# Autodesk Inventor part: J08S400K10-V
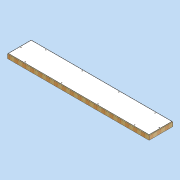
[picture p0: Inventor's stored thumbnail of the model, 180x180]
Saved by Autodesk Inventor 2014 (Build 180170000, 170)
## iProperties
Created: 2011-04
Part Number: J08S400K10-V
Document SubType Name: Modeling
Designer: david.appleford
Density: 1 g/cm^3
Description: Joist Spacer 2w x 400mm Locks 10
Mass: 75032.5 g
Surface Area: 23468.7 cm^2
Volume: 75032.5 cm^3
Cost Center: £95.00
Material: Generic
Appearance: Wood (Pine)
Justset: False
Title: Panel 0.5w x 1w Locks 3
Author: david.appleford
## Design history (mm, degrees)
sketch "Sketch1"
  geometry: L1 (0, 0)-(2440, 0); L2 (2440, 0)-(2440, 468); L3 (2440, 468)-(0, 468); L4 (0, 468)-(0, 0); L5 (34, 434)-(2406, 434); L6 (2406, 434)-(2406, 34); L7 (2406, 34)-(34, 34); L8 (34, 34)-(34, 434)
  constraints: 16 end point, 4 parallel, 2 perpendicular, 1 horizontal, 3 other
  dimensions: "d0" = 2440 distance between parallel lines of L2 L4; "d1" = 468 distance between parallel lines of L1 L3; "d2" = 34 distance between parallel lines of L5 L3 (= 0.5 x t); "d30" = 400 distance between parallel lines of L7 L5 (derived); "d31" = 2372 distance between parallel lines of L6 L8 (derived)
extrude "Extrusion1" new body sketch "Sketch1" distance "d3" = 68 (= t); taper "d4" = 0 deg
sketch "Sketch2"
  geometry: L1 (2406, 434)-(2406, 34) reference; L2 (34, 434)-(2406, 434) reference; L3 (34, 34)-(34, 434) reference; L4 (2406, 34)-(34, 34) reference; L5 (2396, 424)-(2396, 44); L6 (2396, 44)-(44, 44); L7 (44, 44)-(44, 424); L8 (44, 424)-(2396, 424); 1 further point
  constraints: 8 end point, 3 other
  dimensions: "d5" = 10 distance between parallel lines of L8 L2
extrude "Extrusion2" join sketch "Sketch2" distance "d6" = 6 (= sw); taper "d7" = 0 deg
sketch "Sketch3"
  geometry: L1 (-44, 424)-(-2396, 424) reference; L2 (-2396, 424)-(-2396, 44) reference; L3 (-44, 44)-(-44, 424) reference; L4 (-2396, 44)-(-44, 44) reference; 1 further point
extrude "Extrusion3" join sketch "Sketch3" distance "d8" = 6 (= sw); taper "d9" = 0 deg
sketch "Sketch4" dims "d39" = 10
  geometry: L1 (34, 434)-(2406, 434) reference; L2 (2406, 434)-(2406, 34) reference; L3 (2406, 34)-(34, 34) reference; L4 (34, 34)-(34, 434) reference; 11 further points
  constraints: 3 horizontal alignment, 2 vertical alignment, 1 horizontal, 4 other
  dimensions: "d10" = 28 distance from line of point (305, 406) L1 (= k); "d12" = 28 distance from line of L3 point (915, 62) (= k); "d13" = 28 distance from line of point (62, 234) L4 (= k); "d14" = 305 horizontal distance of point (305, 406) point (0, 0) (= 0.25 x w); "d15" = 610 horizontal distance of point (915, 62) point (305, 406) (= 0.5 x w); "d29" = 28 distance from line of L2 point (2378, 234) (= d13); "d32" = 400 distance between parallel lines of L3 L1 (derived); "d33" = 200 distance from line of L1 point (62, 234) (= 0.5 x d32); "d36" = 1220 distance of point (305, 406) point (1525, 406)
hole "Hole1" sketch "Sketch4" at (305, 406), (62, 234), (915, 62), (2378, 234), (915, 406), (305, 62), (1525, 406), (1525, 62), (2135, 406), (2135, 62) diameter "d22" = 12 (= hd); stored, may be unused: countersink angle "d26" = 90 deg, drill point angle "d28" = 118 deg; dims "d23" = 6, "d24" = 4, "d25" = 2, "d27" = 8
sketch "Sketch5"
  geometry: L1 (-2406, 34)-(-34, 34) reference; L2 (-34, 434)-(-2406, 434) reference; L3 (-1176, 34)-(-1264, 34); L4 (-1264, 34)-(-1264, 434); L5 (-1264, 434)-(-1176, 434); L6 (-1176, 434)-(-1176, 34); L7 (-1220, 34)-(-1220, 434); 1 further point
  constraints: 10 end point, 2 midpoint, 2 point on line
  dimensions: "d41" = 1220 distance from line of L7 point (0, 0); "d42" = 88 distance between parallel lines of L4 L6
extrude "Extrusion4" cut sketch "Sketch5" stored distance "d43" = 10; taper "d44" = 0 deg
body "Solid1"
node "Projected Loop1"
other parameters: "t" = 68 [user parameter; used in 2 equation terms], "e" = 16 [user parameter], "sw" = 6 [user parameter; used in 2 equation terms], "sc" = 9 [user parameter], "sf" = 12 [user parameter], "k" = 28 [user parameter; used in 3 equation terms], "hd" = 12 [user parameter; used in 1 equation term]
